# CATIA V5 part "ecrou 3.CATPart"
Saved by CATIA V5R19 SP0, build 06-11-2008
Part number: ecrou 3
Definition: NONE
Nomenclature: 1
Source: Unknown
Description: PART-1-DESC
Bounding box of the stored display mesh (mm): x -3.175 to 3.175, y 0 to 2.4, z -2.75 to 2.75
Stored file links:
  G:\EU_thinkMotion\CFAO_2010\MMS_groupe3\MMS_groupe3\A reprendre\ftixier\florent-tixier\florent-tixier\ecrou 3.CATPart
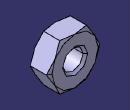
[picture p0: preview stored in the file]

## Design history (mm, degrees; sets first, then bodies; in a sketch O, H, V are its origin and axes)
Body1 "1" (main body)
  Solid1: solid without history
